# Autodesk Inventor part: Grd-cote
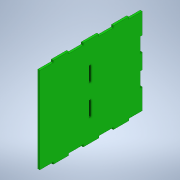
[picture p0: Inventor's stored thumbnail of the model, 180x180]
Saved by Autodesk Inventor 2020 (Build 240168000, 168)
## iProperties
Created: 2023-12
Part Number: Grd-cote
Material: Générique
Document SubType Name: Modeling
Designer: bruno
Density: 1 g/cm^3
Appearance: Vert foncé
Author: bruno
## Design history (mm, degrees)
sketch "Esquisse1"
  geometry: L1 (59.938, 165)-(82.812, 165); L2 (59.938, 162)-(59.938, 165); L3 (37.062, 162)-(59.938, 162); L4 (37.062, 165)-(37.062, 162); L5 (14.188, 165)-(37.062, 165); L6 (14.188, 162)-(14.188, 165); L7 (0, 162)-(14.188, 162); L8 (82.812, 165)-(82.812, 162); L9 (0, 182.812)-(0, 162); L10 (97, 318)-(0, 318); L11 (97, 297.188)-(97, 318); L12 (94, 297.188)-(97, 297.188); L13 (94, 274.312)-(94, 297.188); L14 (97, 274.312)-(94, 274.312); L15 (97, 251.438)-(97, 274.312); L16 (94, 251.438)-(97, 251.438); L17 (94, 228.563)-(94, 251.438); L18 (97, 228.563)-(94, 228.563); L19 (97, 205.688)-(97, 228.563); L20 (94, 205.688)-(97, 205.688); L21 (94, 182.812)-(94, 205.688); L22 (3, 205.688)-(3, 182.812); L23 (0, 205.688)-(3, 205.688); L24 (0, 228.563)-(0, 205.688); L25 (3, 228.563)-(0, 228.563); L26 (3, 182.812)-(0, 182.812); L27 (0, 318)-(0, 297.188); L28 (3, 251.438)-(3, 228.563); L29 (0, 251.438)-(3, 251.438); L30 (0, 274.312)-(0, 251.438); L31 (3, 274.312)-(0, 274.312); L32 (3, 297.188)-(3, 274.312); L33 (0, 297.188)-(3, 297.188); L34 (97, 182.812)-(94, 182.812); L35 (97, 162)-(97, 182.812); L36 (82.812, 162)-(97, 162); L37 (337, 82.938)-(337, 105.812); L38 (243, 60.063)-(240, 60.063); L39 (243, 82.938)-(243, 60.063); L40 (240, 82.938)-(243, 82.938); L41 (240, 105.812)-(240, 82.938); L42 (243, 105.812)-(240, 105.812); L43 (243, 137)-(243, 105.812); L44 (337, 105.812)-(334, 105.812); L45 (334, 105.812)-(334, 128.688); L46 (334, 128.688)-(334, 137); L47 (334, 137)-(322.812, 137); L48 (322.812, 137)-(322.812, 140); L49 (322.812, 140)-(299.938, 140); L50 (299.938, 140)-(299.938, 137); L51 (299.938, 137)-(277.062, 137); L52 (277.062, 137)-(277.062, 140); L53 (277.062, 140)-(254.188, 140); L54 (254.188, 140)-(254.188, 137); L55 (254.188, 137)-(243, 137); L56 (254.188, 6)-(254.188, 3); L57 (243, 6)-(254.188, 6); L58 (243, 14.313)-(243, 6); L59 (243, 37.188)-(243, 14.313); L60 (240, 37.188)-(243, 37.188); L61 (240, 60.063)-(240, 37.188); L62 (277.062, 3)-(277.062, 6); L63 (277.062, 6)-(299.938, 6); L64 (299.938, 6)-(299.938, 3)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; 76 further points
  constraints: 368 end point
extrude "Extrusion2" new body sketch "Esquisse1" distance "d2" = 3; taper "d3" = 0 deg
sketch "Esquisse2"
  geometry: L1 (243, 134.188)-(243, 157.062) reference; L2 (243, 157.062)-(240, 157.062) reference; L3 (240, 134.188)-(240, 157.062) reference; L4 (243, 134.188)-(240, 134.188) reference; L5 (243, 179.938)-(243, 202.812) reference; L6 (243, 202.812)-(240, 202.812) reference; L7 (240, 179.938)-(240, 202.812) reference; L8 (243, 179.938)-(240, 179.938) reference; 1 further point
extrude "Extrusion3" cut sketch "Esquisse2" distance "d4" = 10; taper "d5" = 0 deg
sketch "Esquisse3"
  geometry: L1 (-240, 202.812)-(-240, 179.938) reference; L2 (-240, 179.938)-(-243, 179.938) reference; L3 (-243, 179.938)-(-243, 202.812) reference; L4 (-243, 202.812)-(-240, 202.812) reference; L5 (-243, 134.188)-(-243, 157.062) reference; L6 (-243, 157.062)-(-240, 157.062) reference; L7 (-240, 157.062)-(-240, 134.188) reference; L8 (-240, 134.188)-(-243, 134.188) reference; L9 (-165, 179.938)-(-165, 202.812) reference; L10 (-165, 202.812)-(-162, 202.812) reference; L11 (-162, 202.812)-(-162, 234) reference; L12 (-162, 234)-(-182.812, 234) reference; L13 (-182.812, 234)-(-182.812, 237) reference; L14 (-182.812, 237)-(-205.688, 237) reference; L15 (-205.688, 237)-(-205.688, 234) reference; L16 (-205.688, 234)-(-228.563, 234) reference; L17 (-228.563, 234)-(-228.563, 237) reference; L18 (-228.563, 237)-(-251.438, 237) reference; L19 (-251.438, 237)-(-251.438, 234) reference; L20 (-251.438, 234)-(-274.312, 234) reference; L21 (-274.312, 234)-(-274.312, 237) reference; L22 (-274.312, 237)-(-297.188, 237) reference; L23 (-297.188, 237)-(-297.188, 234) reference; L24 (-297.188, 234)-(-318, 234) reference; L25 (-318, 234)-(-318, 103) reference; L26 (-318, 103)-(-297.188, 103) reference; L27 (-297.188, 103)-(-297.188, 100) reference; L28 (-297.188, 100)-(-274.312, 100) reference; L29 (-274.312, 100)-(-274.312, 103) reference; L30 (-274.312, 103)-(-251.438, 103) reference; L31 (-251.438, 103)-(-251.438, 100) reference; L32 (-251.438, 100)-(-228.563, 100) reference; L33 (-228.563, 100)-(-228.563, 103) reference; L34 (-228.563, 103)-(-205.688, 103) reference; L35 (-205.688, 103)-(-205.688, 100) reference; L36 (-205.688, 100)-(-182.812, 100) reference; L37 (-182.812, 100)-(-182.812, 103) reference; L38 (-182.812, 103)-(-162, 103) reference; L39 (-162, 103)-(-162, 134.188) reference; L40 (-162, 134.188)-(-165, 134.188) reference; L41 (-165, 134.188)-(-165, 157.062) reference; L42 (-165, 157.062)-(-162, 157.062) reference; L43 (-162, 157.062)-(-162, 179.938) reference; L44 (-162, 179.938)-(-165, 179.938) reference; L45 (-297.188, 234)-(-297.488, 234); L46 (-297.488, 234)-(-297.488, 237); L47 (-297.488, 237)-(-297.188, 237); L48 (-297.188, 237)-(-297.188, 234); L49 (-251.438, 234)-(-274.312, 234) reference; L50 (-274.312, 234)-(-274.012, 234); L51 (-274.012, 234)-(-274.012, 237); L52 (-274.012, 237)-(-274.312, 237); L53 (-274.312, 237)-(-274.312, 234); L54 (-251.438, 234)-(-251.738, 234); L55 (-251.738, 234)-(-251.738, 237); L56 (-251.738, 237)-(-251.438, 237); L57 (-251.438, 237)-(-251.438, 234); L58 (-228.563, 234)-(-228.563, 237) reference; L59 (-228.563, 234)-(-228.263, 234); L60 (-228.263, 234)-(-228.263, 237); L61 (-228.263, 237)-(-228.563, 237); L62 (-228.563, 237)-(-228.563, 234); L63 (-205.688, 234)-(-228.563, 234) reference; L64 (-205.688, 234)-(-205.988, 234)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; 29 further points
  constraints: 112 end point, 28 parallel, 14 horizontal, 14 perpendicular, 11 point on line
  dimensions: "d6" = 0.3 distance of L46.end L47.end; "d7" = 0.3 distance of L52.end L51.end; "d8" = 0.3 distance of L55.end L56.end; "d9" = 0.3 distance of L61.end L60.end; "d10" = 0.3 distance of L65.end L66.end; "d11" = 0.3 distance of L71.end L70.end; "d12" = 0.2 distance of L75.end L74.end; "d13" = 0.2 distance of L79.end L80.end; "d14" = 0.3 distance of L85.end L84.end; "d15" = 0.3 distance of L89.end L90.end; "d16" = 0.3 distance of L95.end L94.end; "d17" = 0.3 distance of L98.end L99.end; "d18" = 0.3 distance of L104.end L103.end; "d19" = 0.3 distance of L108.end L109.end
extrude "Extrusion4" join sketch "Esquisse3" distance "d20" = 3; taper "d21" = 0 deg
sketch "Esquisse4"
  geometry: L1 (-240, 202.812)-(-240, 179.938) reference; L2 (-240, 179.938)-(-243, 179.938) reference; L3 (-243, 179.938)-(-243, 202.812) reference; L4 (-243, 202.812)-(-240, 202.812) reference; L5 (-243, 134.188)-(-243, 157.062) reference; L6 (-243, 157.062)-(-240, 157.062) reference; L7 (-240, 157.062)-(-240, 134.188) reference; L8 (-240, 134.188)-(-243, 134.188) reference; L9 (-165, 180.138)-(-165, 202.812) reference; L10 (-165, 202.812)-(-162, 202.812) reference; L11 (-162, 202.812)-(-162, 234) reference; L12 (-162, 234)-(-182.512, 234) reference; L13 (-182.512, 234)-(-182.512, 237) reference; L14 (-182.512, 237)-(-205.988, 237) reference; L15 (-205.988, 237)-(-205.988, 234) reference; L16 (-205.988, 234)-(-228.263, 234) reference; L17 (-228.263, 234)-(-228.263, 237) reference; L18 (-228.263, 237)-(-251.738, 237) reference; L19 (-251.738, 237)-(-251.738, 234) reference; L20 (-251.738, 234)-(-274.012, 234) reference; L21 (-274.012, 234)-(-274.012, 237) reference; L22 (-274.012, 237)-(-297.488, 237) reference; L23 (-297.488, 237)-(-297.488, 234) reference; L24 (-297.488, 234)-(-318, 234) reference; L25 (-318, 234)-(-318, 103) reference; L26 (-318, 103)-(-297.488, 103) reference; L27 (-297.488, 103)-(-297.488, 100) reference; L28 (-297.488, 100)-(-274.012, 100) reference; L29 (-274.012, 100)-(-274.012, 103) reference; L30 (-274.012, 103)-(-251.738, 103) reference; L31 (-251.738, 103)-(-251.738, 100) reference; L32 (-251.738, 100)-(-228.263, 100) reference; L33 (-228.263, 100)-(-228.263, 103) reference; L34 (-228.263, 103)-(-205.988, 103) reference; L35 (-205.988, 103)-(-205.988, 100) reference; L36 (-205.988, 100)-(-182.512, 100) reference; L37 (-182.512, 100)-(-182.512, 103) reference; L38 (-182.512, 103)-(-162, 103) reference; L39 (-162, 103)-(-162, 134.188) reference; L40 (-162, 134.188)-(-165, 134.188) reference; L41 (-165, 134.188)-(-165, 156.863) reference; L42 (-165, 156.863)-(-162, 156.863) reference; L43 (-162, 156.863)-(-162, 180.138) reference; L44 (-162, 180.138)-(-165, 180.138) reference; L45 (-165, 202.812)-(-162, 202.812) reference; L46 (-165, 202.812)-(-162, 202.812); L47 (-162, 202.812)-(-162, 202.512); L48 (-162, 202.512)-(-165, 202.512); L49 (-165, 202.512)-(-165, 202.812); L50 (-165, 134.188)-(-165, 156.863) reference; L51 (-165, 134.188)-(-162, 134.188); L52 (-162, 134.188)-(-162, 134.488); L53 (-162, 134.488)-(-165, 134.487); L54 (-165, 134.487)-(-165, 134.188); 5 further points
  constraints: 16 end point, 4 parallel, 2 horizontal, 2 perpendicular, 1 point on line
  dimensions: "d22" = 0.3 distance of L46.end L47.end; "d23" = 0.3 distance of L52.end L51.end
extrude "Extrusion5" join sketch "Esquisse4" distance "d24" = 3; taper "d25" = 0 deg
node "Solide2"
node "Référence1"
node "Référence2"
node "Boucle projetée1"
node "Boucle projetée2"
